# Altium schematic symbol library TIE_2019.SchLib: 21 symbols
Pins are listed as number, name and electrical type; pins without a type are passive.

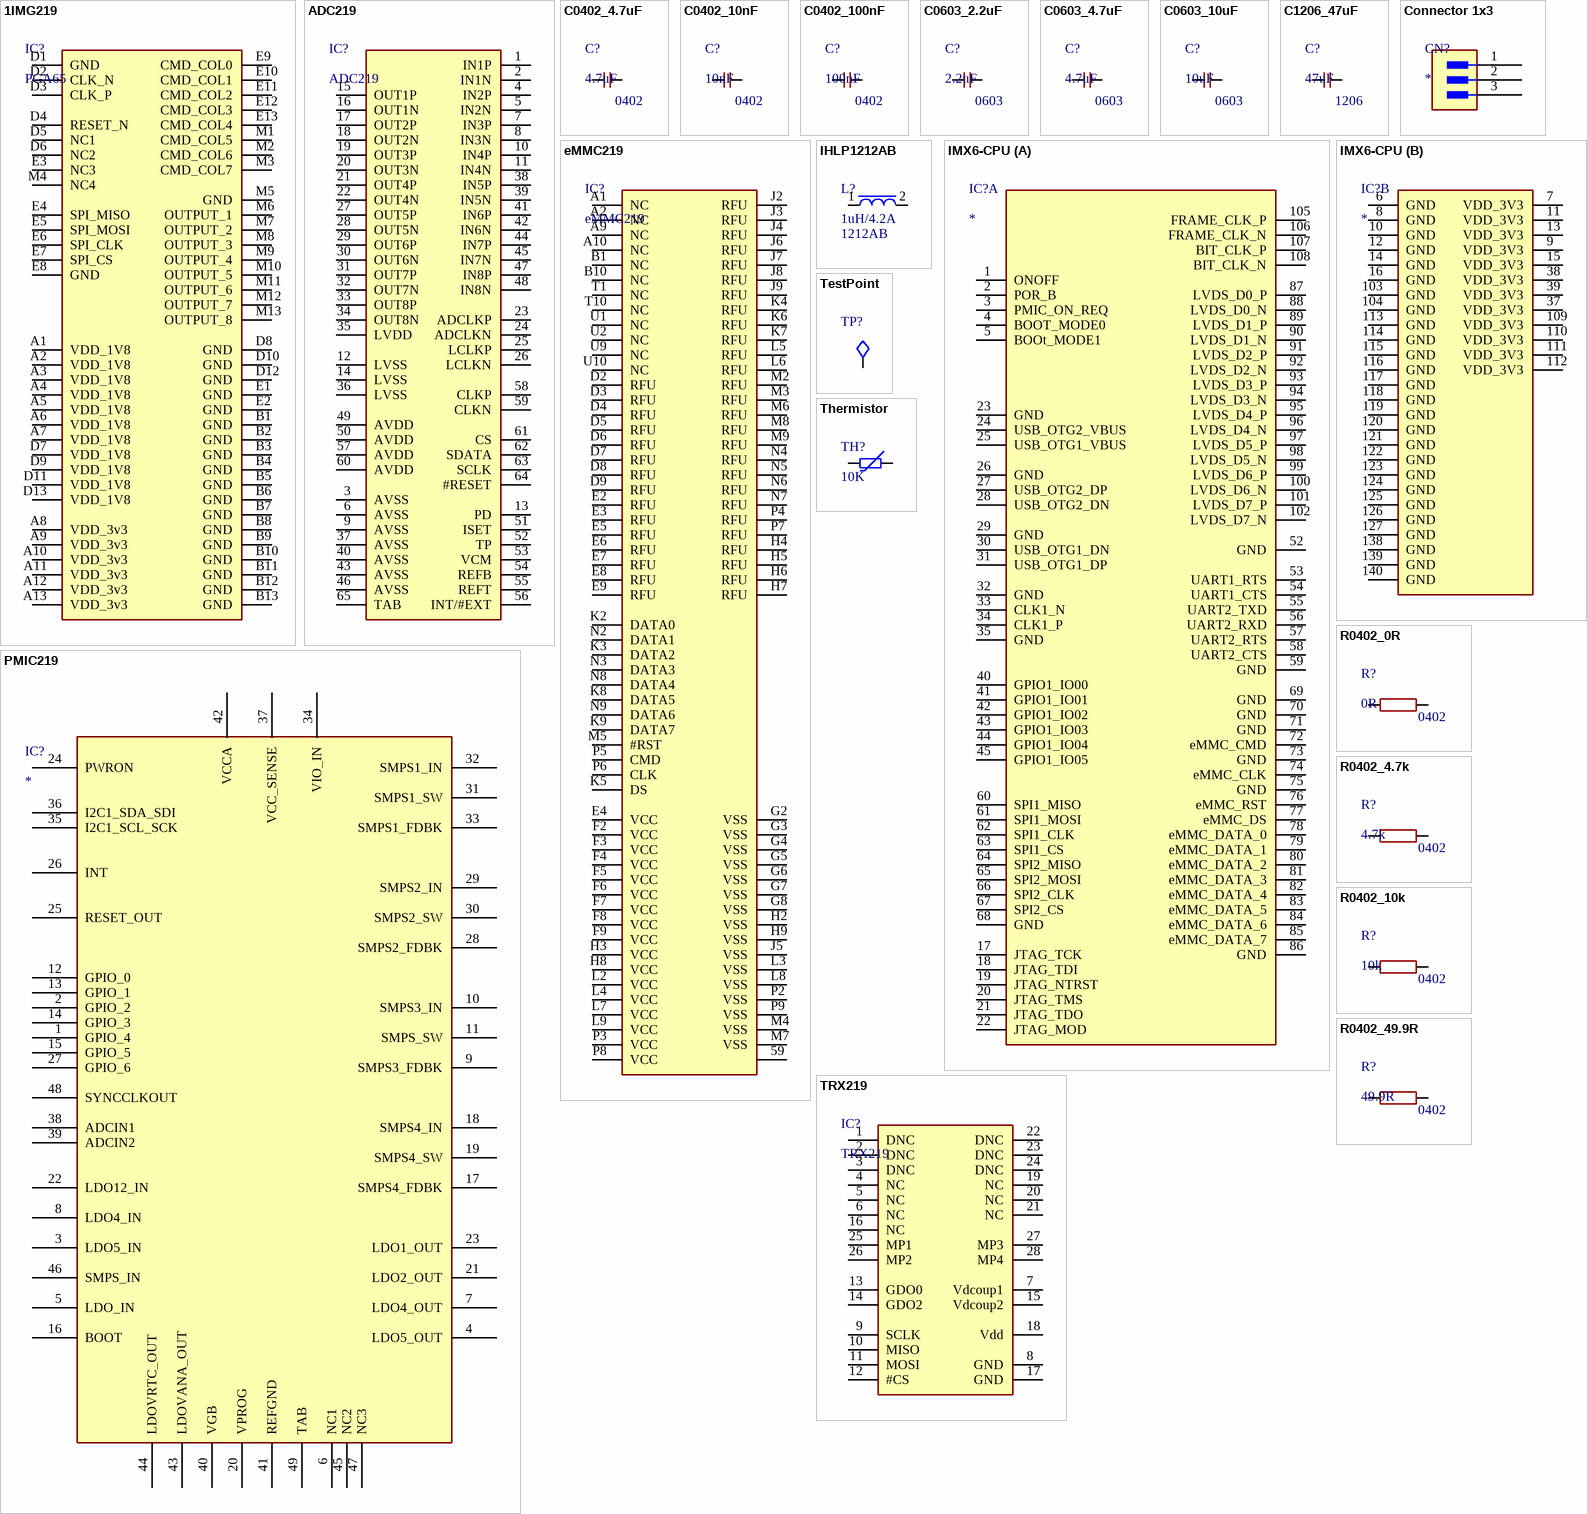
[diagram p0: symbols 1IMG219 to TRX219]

## 1IMG219
designator IC?, comment PGA65
footprint PGAx13
pins: A1 VDD_1V8, A2 VDD_1V8, A3 VDD_1V8, A4 VDD_1V8, A5 VDD_1V8, A6 VDD_1V8, A7 VDD_1V8, A8 VDD_3v3, A9 VDD_3v3, A10 VDD_3v3, A11 VDD_3v3, A12 VDD_3v3, A13 VDD_3v3, B1 GND, B2 GND, B3 GND, B4 GND, B5 GND, B6 GND, B7 GND, B8 GND, B9 GND, B10 GND, B11 GND, B12 GND, B13 GND, D1 GND, D2 CLK_N, D3 CLK_P, D4 RESET_N, D5 NC1, D6 NC2, D7 VDD_1V8, D8 GND, D9 VDD_1V8, D10 GND, D11 VDD_1V8, D12 GND, D13 VDD_1V8, E1 GND, E2 GND, E3 NC3, E4 SPI_MISO, E5 SPI_MOSI, E6 SPI_CLK, E7 SPI_CS, E8 GND, E9 CMD_COL0, E10 CMD_COL1, E11 CMD_COL2, E12 CMD_COL3, E13 CMD_COL4, M1 CMD_COL5, M2 CMD_COL6, M3 CMD_COL7, M4 NC4, M5 GND, M6 OUTPUT_1, M7 OUTPUT_2, M8 OUTPUT_3, M9 OUTPUT_4, M10 OUTPUT_5, M11 OUTPUT_6, M12 OUTPUT_7, M13 OUTPUT_8

## ADC219
designator IC?
footprint QFN64 (QFN, 64-Leads, Body 9.00x9.00mm, Pitch 0.50mm, Thermal Pad 7.25x7.25mm, IPC Medium Density)
pins: 1 IN1P, 2 IN1N, 3 AVSS, 4 IN2P, 5 IN2N, 6 AVSS, 7 IN3P, 8 IN3N, 9 AVSS, 10 IN4P, 11 IN4N, 12 LVSS, 13 PD, 14 LVSS, 15 OUT1P, 16 OUT1N, 17 OUT2P, 18 OUT2N, 19 OUT3P, 20 OUT3N, 21 OUT4P, 22 OUT4N, 23 ADCLKP, 24 ADCLKN, 25 LCLKP, 26 LCLKN, 27 OUT5P, 28 OUT5N, 29 OUT6P, 30 OUT6N, 31 OUT7P, 32 OUT7N, 33 OUT8P, 34 OUT8N, 35 LVDD, 36 LVSS, 37 AVSS, 38 IN5P, 39 IN5N, 40 AVSS, 41 IN6P, 42 IN6N, 43 AVSS, 44 IN7P, 45 IN7N, 46 AVSS, 47 IN8P, 48 IN8N, 49 AVDD, 50 AVDD, 51 ISET, 52 TP, 53 VCM, 54 REFB, 55 REFT, 56 INT/#EXT, 57 AVDD, 58 CLKP, 59 CLKN, 60 AVDD, 61 CS, 62 SDATA, 63 SCLK, 64 #RESET, 65 TAB

## C0402_4.7uF
designator C?, comment 4.7uF  Footprint Name: 0402
CAP CER 4.7upF SMD 0402; Manufacturer: Murata; Manufacturer Part Number: GJM1555C1H100JB01D; Parameter 1: 50V
footprint CAP0402
pins: 1, 2

## C0402_10nF
designator C?, comment 10nF  Footprint Name: 0402
CAP CER 10nF SMD 0402; Manufacturer: Murata; Manufacturer Part Number: GJM1555C1H100JB01D; Parameter 1: 50V
footprint CAP0402
pins: 1, 2

## C0402_100nF
designator C?, comment 100nF  Footprint Name: 0402
CAP CER 100nF SMD 0402; Manufacturer: Murata; Manufacturer Part Number: GJM1555C1H100JB01D; Parameter 1: 50V
footprint CAP0402
pins: 1, 2

## C0603_2.2uF
designator C?, comment 2.2uF  Footprint Name: 0603
CAP CER 2.2uF  SMD 0603; Manufacturer: Murata; Manufacturer Part Number: GJM1555C1H100JB01D
footprint CAP0603
pins: 1, 2

## C0603_4.7uF
designator C?, comment 4.7uF  Footprint Name: 0603
CAP CER 4.7uF  SMD 0603; Manufacturer: Murata; Manufacturer Part Number: GJM1555C1H100JB01D
footprint CAP0603
pins: 1, 2

## C0603_10uF
designator C?, comment 10uF  Footprint Name: 0603
CAP CER 10uF  SMD 0603; Manufacturer: Murata; Manufacturer Part Number: GJM1555C1H100JB01D
footprint CAP0603
pins: 1, 2

## C1206_47uF
designator C?, comment 47uF  Footprint Name: 1206
CAP CER 47uF  SMD 1206; Manufacturer: Murata; Manufacturer Part Number: GJM1555C1H100JB01D
footprint CAP1206
pins: 1, 2

## Connector 1x3
designator CN?
footprint Conn1x03
pins: 1, 2, 3

## eMMC219
designator IC?
BGA100
footprint BGA100 (BGA, 100-Leads, Body 14.00x18.00mmx1.40mm, Pitch 1.00mm)
pins: 59, A1 NC, A2 NC, A9 NC, A10 NC, B1 NC, B10 NC, D2 RFU, D3 RFU, D4 RFU, D5 RFU, D6 RFU, D7 RFU, D8 RFU, D9 RFU, E2 RFU, E3 RFU, E4 VCC, E5 RFU, E6 RFU, E7 RFU, E8 RFU, E9 RFU, F2 VCC, F3 VCC, F4 VCC, F5 VCC, F6 VCC, F7 VCC, F8 VCC, F9 VCC, G2 VSS, G3 VSS, G4 VSS, G5 VSS, G6 VSS, G7 VSS, G8 VSS, H2 VSS, H3 VCC, H4 RFU, H5 RFU, H6 RFU, H7 RFU, H8 VCC, H9 VSS, J2 RFU, J3 RFU, J4 RFU, J5 VSS, J6 RFU, J7 RFU, J8 RFU, J9 RFU, K2 DATA0, K3 DATA2, K4 RFU, K5 DS, K6 RFU, K7 RFU, K8 DATA5, K9 DATA7, L2 VCC, L3 VSS, L4 VCC, L5 RFU, L6 RFU, L7 VCC, L8 VSS, L9 VCC, M2 RFU, M3 RFU, M4 VSS, M5 #RST, M6 RFU, M7 VSS, M8 RFU, M9 RFU, N2 DATA1, N3 DATA3, N4 RFU, N5 RFU, N6 RFU, N7 RFU, N8 DATA4, N9 DATA6, P2 VSS, P3 VCC, P4 RFU, P5 CMD, P6 CLK, P7 RFU, P8 VCC, P9 VSS, T1 NC, T10 NC, U1 NC, U2 NC, U9 NC, U10 NC

## IHLP1212AB
designator L?, comment 1uH/4.2A  Footprint: 1212AB
footprint L_1212AB
pins: 1, 2

## IMX6-CPU
designator IC?
528MHz NXP i.MX 6UL/6ULL ARM Cortex-A7 Processors
footprint IMX6-SoM
part A pins: 1 ONOFF, 2 POR_B, 3 PMIC_ON_REQ, 4 BOOT_MODE0, 5 BOOt_MODE1, 17 JTAG_TCK, 18 JTAG_TDI, 19 JTAG_NTRST, 20 JTAG_TMS, 21 JTAG_TDO, 22 JTAG_MOD, 23 GND, 24 USB_OTG2_VBUS, 25 USB_OTG1_VBUS, 26 GND, 27 USB_OTG2_DP, 28 USB_OTG2_DN, 29 GND, 30 USB_OTG1_DN, 31 USB_OTG1_DP, 32 GND, 33 CLK1_N, 34 CLK1_P, 35 GND, 40 GPIO1_IO00, 41 GPIO1_IO01, 42 GPIO1_IO02, 43 GPIO1_IO03, 44 GPIO1_IO04, 45 GPIO1_IO05, 52 GND, 53 UART1_RTS, 54 UART1_CTS, 55 UART2_TXD, 56 UART2_RXD, 57 UART2_RTS, 58 UART2_CTS, 59 GND, 60 SPI1_MISO, 61 SPI1_MOSI, 62 SPI1_CLK, 63 SPI1_CS, 64 SPI2_MISO, 65 SPI2_MOSI, 66 SPI2_CLK, 67 SPI2_CS, 68 GND, 69 GND, 70 GND, 71 GND, 72 eMMC_CMD, 73 GND, 74 eMMC_CLK, 75 GND, 76 eMMC_RST, 77 eMMC_DS, 78 eMMC_DATA_0, 79 eMMC_DATA_1, 80 eMMC_DATA_2, 81 eMMC_DATA_3, 82 eMMC_DATA_4, 83 eMMC_DATA_5, 84 eMMC_DATA_6, 85 eMMC_DATA_7, 86 GND, 87 LVDS_D0_P, 88 LVDS_D0_N, 89 LVDS_D1_P, 90 LVDS_D1_N, 91 LVDS_D2_P, 92 LVDS_D2_N, 93 LVDS_D3_P, 94 LVDS_D3_N, 95 LVDS_D4_P, 96 LVDS_D4_N, 97 LVDS_D5_P, 98 LVDS_D5_N, 99 LVDS_D6_P, 100 LVDS_D6_N, 101 LVDS_D7_P, 102 LVDS_D7_N, 105 FRAME_CLK_P, 106 FRAME_CLK_N, 107 BIT_CLK_P, 108 BIT_CLK_N
part B pins: 6 GND, 7 VDD_3V3, 8 GND, 9 VDD_3V3, 10 GND, 11 VDD_3V3, 12 GND, 13 VDD_3V3, 14 GND, 15 VDD_3V3, 16 GND, 37 VDD_3V3, 38 VDD_3V3, 39 VDD_3V3, 103 GND, 104 GND, 109 VDD_3V3, 110 VDD_3V3, 111 VDD_3V3, 112 VDD_3V3, 113 GND, 114 GND, 115 GND, 116 GND, 117 GND, 118 GND, 119 GND, 120 GND, 121 GND, 122 GND, 123 GND, 124 GND, 125 GND, 126 GND, 127 GND, 138 GND, 139 GND, 140 GND

## PMIC219
designator IC?
footprint 48-QFN (6x6mm QFN Package)
pins: 1 GPIO_4, 2 GPIO_2, 3 LDO5_IN, 4 LDO5_OUT, 5 LDO_IN, 6 NC1, 7 LDO4_OUT, 8 LDO4_IN, 9 SMPS3_FDBK, 10 SMPS3_IN, 11 SMPS_SW, 12 GPIO_0, 13 GPIO_1, 14 GPIO_3, 15 GPIO_5, 16 BOOT, 17 SMPS4_FDBK, 18 SMPS4_IN, 19 SMPS4_SW, 20 VPROG, 21 LDO2_OUT, 22 LDO12_IN, 23 LDO1_OUT, 24 PWRON, 25 RESET_OUT, 26 INT, 27 GPIO_6, 28 SMPS2_FDBK, 29 SMPS2_IN, 30 SMPS2_SW, 31 SMPS1_SW, 32 SMPS1_IN, 33 SMPS1_FDBK, 34 VIO_IN, 35 I2C1_SCL_SCK, 36 I2C1_SDA_SDI, 37 VCC_SENSE, 38 ADCIN1, 39 ADCIN2, 40 VGB, 41 REFGND, 42 VCCA, 43 LDOVANA_OUT, 44 LDOVRTC_OUT, 45 NC2, 46 SMPS_IN, 47 NC3, 48 SYNCCLKOUT, 49 TAB

## R0402_0R
designator R?, comment 0R  Footprint Name: 0402
RES TKF 0R  SMD 0402; Manufacturer: TE Connectivity; Manufacturer Part Number: CRG0402F10K; Tolerance: 1%
footprint RES0402
pins: 1, 2

## R0402_4.7k
designator R?, comment 4.7k  Footprint Name: 0402
RES TKF 4.7k SMD 0402; Manufacturer: TE Connectivity; Manufacturer Part Number: CRG0402F10K; Tolerance: 1%
footprint RES0402
pins: 1, 2

## R0402_10k
designator R?, comment 10k  Footprint Name: 0402
RES TKF 10k  SMD 0402; Manufacturer: TE Connectivity; Manufacturer Part Number: CRG0402F10K; Tolerance: 1%
footprint RES0402
pins: 1, 2

## R0402_49.9R
designator R?, comment 49.9R  Footprint Name: 0402
RES TKF 49.9R SMD 0402; Manufacturer: TE Connectivity; Manufacturer Part Number: CRG0402F10K; Tolerance: 1%
footprint RES0402
pins: 1, 2

## TestPoint
designator TP?  (value not drawn)  (no BOM)
SMD test point; Manufacturer: NA; .Checked_PCB: AI; .Creator: RV
footprint TestPoint_2019
pins: 1

## Thermistor
designator TH?, comment 10K
THERMISTOR 10K OHM  0402
footprint RES0402
pins: 1, 2

## TRX219
designator IC?
MOD26
footprint A1101R09C00GM (Sub-GHz Modules 900MHz Radio Only Connector)
pins: 1 DNC, 2 DNC, 3 DNC, 4 NC, 5 NC, 6 NC, 7 Vdcoup1, 8 GND, 9 SCLK, 10 MISO, 11 MOSI, 12 #CS, 13 GDO0, 14 GDO2, 15 Vdcoup2, 16 NC, 17 GND, 18 Vdd, 19 NC, 20 NC, 21 NC, 22 DNC, 23 DNC, 24 DNC, 25 MP1, 26 MP2, 27 MP3, 28 MP4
